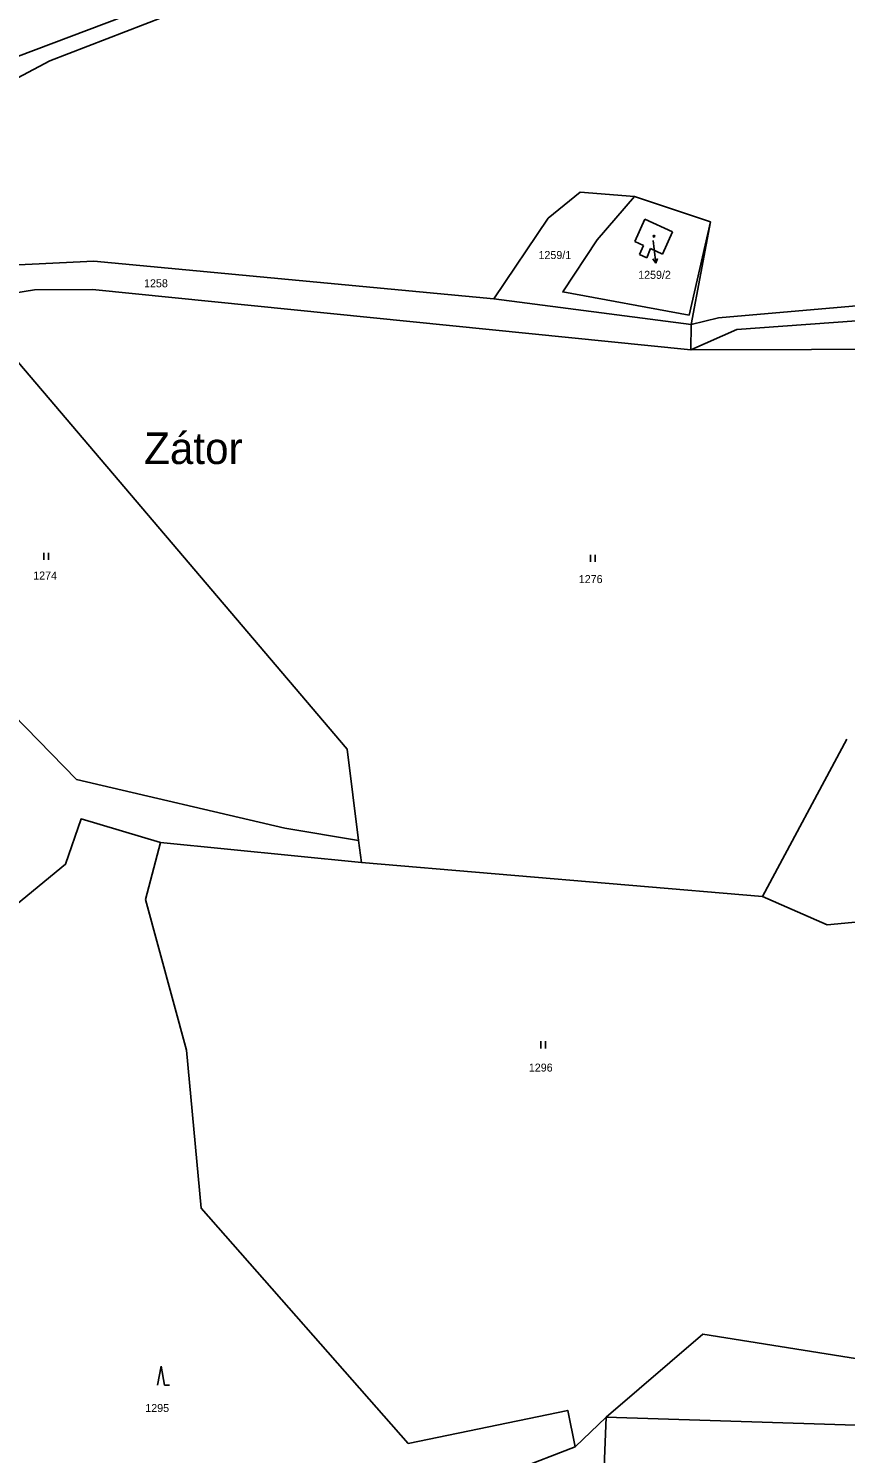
# Model space of a CAD drawing. Extents: x -520431 to -517205, y -1075927 to -1074013.
# Drawn here: x -517800.7 to -517627.2, y -1075007.9 to -1074705.2 of the extents above; entities that cross this region are included whole.
import ezdxf

# ---------------------------------------------------------------- set-up
doc = ezdxf.new("R2010")
doc.units = 0
for name, color, linetype in [('Hranice parcel', 7, 'Continuous'), ('Parcelní čísla', 7, 'Continuous'), ('Pop  PČ popisy', 7, 'Continuous'), ('Vnitřní kresba', 7, 'Continuous'), ('Vrstva 54', 7, 'Continuous'), ('Značky budov', 7, 'Continuous'), ('Značky kultur', 7, 'Continuous')]:
    doc.layers.add(name, color=color, linetype=linetype)

msp = doc.modelspace()

# ---------------------------------------------------------------- linework, layer by layer
at = {"layer": 'Hranice parcel'}
for p, q in [((-517672, -1074740.91), (-517655.89, -1074746.33)), ((-517655.89, -1074746.33), (-517660, -1074768.08)), ((-517660, -1074768.08), (-517701.89, -1074762.67)), ((-517660.04, -1074773.47), (-517660, -1074768.08)), ((-517644.8, -1074889.6), (-517626.95, -1074856.18)), ((-517772.7, -1074878.11), (-517730.02, -1074882.38)), ((-517730.02, -1074882.38), (-517730.61, -1074877.68)), ((-517730.02, -1074882.38), (-517644.8, -1074889.6)), ((-517684.65, -1075006.47), (-517678.03, -1075000.2))]:
    msp.add_line(p, q, dxfattribs=at)
for points in [[(-517808.22, -1074713.87), (-517802.82, -1074711.12), (-517769.64, -1074698.49), (-517753.22, -1074689.81), (-517717.47, -1074668.36), (-517700.27, -1074656.19), (-517669.54, -1074626.83), (-517660.64, -1074616.44), (-517645.03, -1074592.04), (-517634.84, -1074572.98), (-517631.58, -1074564.18), (-517630.68, -1074555.36)], [(-517830.32, -1074762.49), (-517815.05, -1074725.17), (-517810, -1074719.37), (-517796.16, -1074712.07), (-517767.96, -1074701.22), (-517740.26, -1074686.25), (-517698.1, -1074659.55), (-517684.35, -1074647.39), (-517666.49, -1074628.12), (-517658.4, -1074617.73), (-517642.13, -1074593.59), (-517632.17, -1074575.15), (-517628.34, -1074564.49), (-517627.46, -1074556.34)], [(-517701.89, -1074762.67), (-517690.34, -1074745.53), (-517683.53, -1074739.98), (-517672, -1074740.91)], [(-517655.89, -1074746.33), (-517660.41, -1074766.12), (-517687.26, -1074761.19), (-517679.95, -1074750.09), (-517672, -1074740.91)], [(-517660, -1074768.08), (-517654.16, -1074766.7), (-517584.99, -1074760.67), (-517556.63, -1074753.66), (-517508.94, -1074746.11), (-517435.3, -1074744.53), (-517381.92, -1074748.9)], [(-517660.04, -1074773.47), (-517650.26, -1074769.19), (-517584.81, -1074764.44), (-517509.78, -1074749.3), (-517436.37, -1074749.53), (-517420.59, -1074753.71)], [(-517701.89, -1074762.67), (-517786.84, -1074754.67), (-517813.14, -1074755.9), (-517823.35, -1074758.83), (-517830.32, -1074762.49)], [(-517420.59, -1074753.71), (-517448.28, -1074757.11), (-517518.68, -1074760.42), (-517583.27, -1074773.25), (-517660.04, -1074773.47)], [(-517820.08, -1074764.05), (-517799.41, -1074760.72), (-517787.12, -1074760.67), (-517660.04, -1074773.47)], [(-517730.61, -1074877.68), (-517733.03, -1074858.33), (-517810.28, -1074767.57), (-517814.84, -1074765.93)], [(-517730.61, -1074877.68), (-517746.29, -1074875.07), (-517790.51, -1074864.73), (-517822.83, -1074831.65), (-517836.67, -1074791.87), (-517835.79, -1074783.73)], [(-517823.83, -1074908.18), (-517792.88, -1074882.75), (-517789.56, -1074873.12), (-517772.7, -1074878.11)], [(-517684.65, -1075006.47), (-517686.19, -1074998.75), (-517720.06, -1075005.75), (-517764.04, -1074955.81), (-517767.19, -1074922.26), (-517775.85, -1074890.23), (-517772.7, -1074878.11)], [(-517678.03, -1075000.2), (-517657.48, -1074982.54), (-517600.21, -1074991.68), (-517541.97, -1074899.41), (-517544.37, -1074894.62), (-517590.13, -1074891.7), (-517631.12, -1074895.59), (-517644.8, -1074889.6)], [(-517662.42, -1075096.28), (-517680.93, -1075072.7), (-517678.03, -1075000.2)], [(-517678.03, -1075000.2), (-517561.02, -1075003.93), (-517444, -1075007.65)], [(-517706.64, -1075024.44), (-517697.44, -1075011.46), (-517684.65, -1075006.47)]]:
    msp.add_lwpolyline(points, dxfattribs=at)
at = {"layer": 'Pop  PČ popisy'}
for p, q in [((-517668.08, -1074750.29), (-517667.85, -1074752.13)), ((-517667.85, -1074752.13), (-517667.48, -1074755.11)), ((-517667.48, -1074755.11), (-517668.1, -1074754.18)), ((-517667.48, -1074755.11), (-517667.11, -1074754.05))]:
    msp.add_line(p, q, dxfattribs=at)
at = {"layer": 'Vnitřní kresba'}
for p, q in [((-517671.95, -1074750.46), (-517669.8, -1074745.75)), ((-517669.8, -1074745.75), (-517663.92, -1074748.44)), ((-517663.92, -1074748.44), (-517666.06, -1074753.15)), ((-517670.13, -1074751.29), (-517671.95, -1074750.46)), ((-517670.93, -1074753.26), (-517670.13, -1074751.29)), ((-517668.62, -1074751.98), (-517669.43, -1074753.94)), ((-517666.06, -1074753.15), (-517668.62, -1074751.98)), ((-517669.43, -1074753.94), (-517670.93, -1074753.26))]:
    msp.add_line(p, q, dxfattribs=at)
at = {"layer": 'Vrstva 54'}
msp.add_lwpolyline([(-517769.64, -1074698.49), (-517802.82, -1074711.12)], dxfattribs=at)
at = {"layer": 'Značky budov'}
msp.add_circle((-517667.86, -1074749.35), 0.175, dxfattribs=at)
at = {"layer": 'Značky kultur'}
for p, q in [((-517797.48, -1074818.07), (-517797.48, -1074816.57)), ((-517796.48, -1074818.07), (-517796.48, -1074816.57)), ((-517681.39, -1074818.5), (-517681.39, -1074817)), ((-517680.39, -1074818.5), (-517680.39, -1074817)), ((-517691.94, -1074921.86), (-517691.94, -1074920.36)), ((-517690.94, -1074921.86), (-517690.94, -1074920.36)), ((-517772.55, -1074989.38), (-517773.3, -1074993.38)), ((-517771.8, -1074993.38), (-517772.55, -1074989.38)), ((-517771.8, -1074993.38), (-517770.8, -1074993.38))]:
    msp.add_line(p, q, dxfattribs=at)

# ---------------------------------------------------------------- texts
at = {"layer": 'Parcelní čísla'}
for s, p in [('1259/1', (-517692.41, -1074754.2)), ('1258', (-517776.18, -1074760.2)), ('1259/2', (-517671.24, -1074758.4)), ('1274', (-517799.72, -1074822.28)), ('1276', (-517683.85, -1074823.03)), ('1296', (-517694.46, -1074926.79)), ('1295', (-517775.92, -1074999.1))]:
    msp.add_text(s, height=1.7, dxfattribs=at).set_placement(p)
at = {"layer": 'Pop  PČ popisy'}
msp.add_text('Zátor', height=6.7, dxfattribs=at).set_placement((-517776.16, -1074797.74))

doc.saveas('drawing.dxf')
